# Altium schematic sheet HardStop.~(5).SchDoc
size A
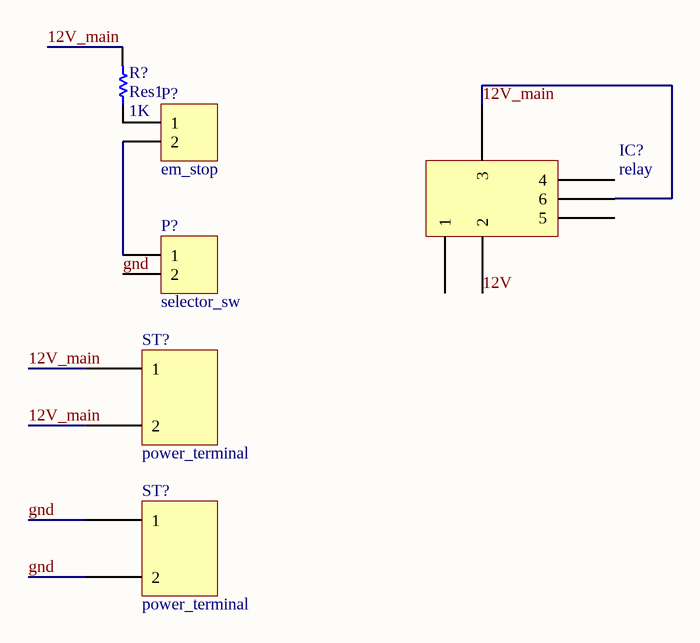
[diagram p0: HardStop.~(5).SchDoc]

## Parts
(Parts that share a designator on the sheet are numbered #1, #2 ... from top to bottom, then left to right.)
IC?  relay  [relay JQX 15F]
P?#1  em_stop  [HDR1X2H]
P?#2  selector_sw  [HDR1X2H]
R?  Res1  value 1K  [AXIAL-0.3]
ST?#1  power_terminal  [screw_terminal_5]
ST?#2  power_terminal  [screw_terminal_5]

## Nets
12V: IC?.2
12V_main: IC?.3 IC?.6 R?.2 ST?#1.1 ST?#1.2
gnd: P?#2.2 ST?#2.1 ST?#2.2
NetP?#1_1: P?#1.1 R?.1
NetP?#1_2: P?#1.2 P?#2.1

Not connected (* = marked no-connect by the designer): IC? 1 4 5

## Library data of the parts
IC? = relay JQX-15F
P?#1 P?#2 = Header 2H: Header, 2-Pin, Right Angle
R? = Res1: Resistor
ST?#1 ST?#2 = screw_terminal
